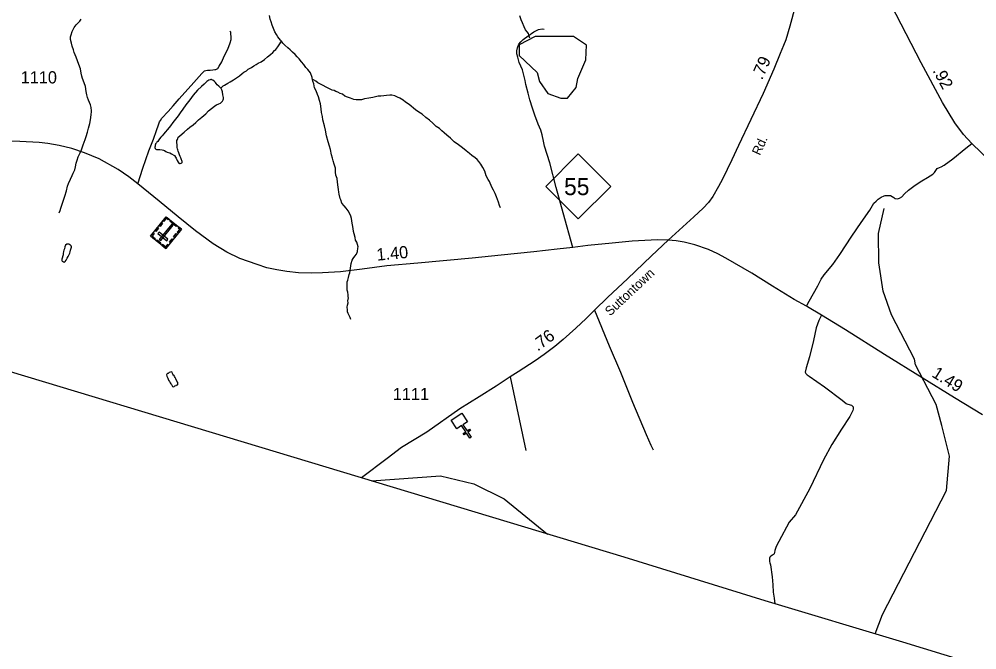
# Model space of a CAD drawing. Extents: x 2206922 to 2357709, y 510027 to 673830.
# Drawn here: x 2238043 to 2247869, y 531268 to 537738 of the extents above; entities that cross this region are included whole.
import ezdxf

# ---------------------------------------------------------------- set-up
doc = ezdxf.new("R2010")
doc.units = 0
for name, color, linetype in [('Exist Boundary Political CountyLine', 7, 'Continuous'), ('Exist Cultural Cemetery CELL', 7, 'Continuous'), ('Exist Cultural Church CELL', 7, 'Continuous'), ('Exist Hydrographic Creek Single Shore', 7, 'Continuous'), ('Exist Hydrographic Misc Water Feature', 7, 'Continuous'), ('Exist Hydrographic Pond Under 1500 Sq Ft', 7, 'Continuous'), ('Exist Road Non-System Type 51', 7, 'Continuous'), ('Exist Road Primary NC Attributed', 7, 'Continuous'), ('Exist Road Primary NC Service Mileage Hundredths English Label', 7, 'Continuous'), ('Exist Road Primary NC Shield CELL', 7, 'Continuous'), ('Exist Road Primary NC Shield Number Label', 7, 'Continuous'), ('Exist Road Secondary Mileage Hundredths English Label', 7, 'Continuous'), ('Exist Road Secondary Type 51 Attributed', 7, 'Continuous'), ('Exist Road Secondary Type 51 Label', 7, 'Continuous'), ('Exist Road Secondary Type 51 Number Label', 7, 'Continuous')]:
    doc.layers.add(name, color=color, linetype=linetype)

msp = doc.modelspace()

# ---------------------------------------------------------------- linework, layer by layer
at = {"layer": 'Exist Boundary Political CountyLine'}
msp.add_lwpolyline([(2249888.1, 524898.7), (2249941, 525530.8), (2250030.4, 526573), (2250196.9, 528467.4), (2250367.4, 530347.8), (2247109, 531346.9), (2245696.1, 531771.2), (2244251.2, 532217.2), (2233874.7, 535351.4), (2230309.4, 536443.8), (2228714.2, 536942.6), (2228202.8, 537099.5)], dxfattribs=at)
at = {"layer": 'Exist Cultural Cemetery CELL'}
for points in [[(2239547.8, 535386.5), (2239392.7, 535511.3), (2239552.3, 535709.7), (2239707.4, 535584.9)], [(2239578.1, 535689), (2239570.9, 535680), (2239553.8, 535693.8), (2239528.4, 535662.3), (2239519.8, 535669.3), (2239552.3, 535709.7)], [(2239474.5, 535594.9), (2239447.4, 535561.2), (2239438.5, 535568.3), (2239465.6, 535602.1)], [(2239515.8, 535646.3), (2239488.7, 535612.5), (2239479.8, 535619.7), (2239507, 535653.4)], [(2239481.2, 535477.7), (2239495.8, 535466), (2239622.9, 535624), (2239608.3, 535635.7)], [(2239655.4, 535612), (2239589.3, 535665.2), (2239596.5, 535674.1), (2239662.6, 535620.9)], [(2239681.6, 535605.6), (2239674.4, 535596.7), (2239691.5, 535582.9), (2239666.2, 535551.4), (2239674.9, 535544.4), (2239707.4, 535584.9)], [(2239419.8, 535545.2), (2239428.6, 535538), (2239408.5, 535513), (2239440.1, 535487.5), (2239433.1, 535478.9), (2239392.7, 535511.4)], [(2239558.7, 535465.1), (2239570.4, 535479.7), (2239478.6, 535553.5), (2239466.9, 535538.9)], [(2239663.6, 535530.4), (2239636.4, 535496.7), (2239627.6, 535503.8), (2239654.7, 535537.5)], [(2239490.1, 535433), (2239449.7, 535465.5), (2239456.9, 535474.3), (2239497.2, 535441.9)], [(2239575, 535420.3), (2239566.1, 535427.4), (2239545.9, 535402.3), (2239514.3, 535427.7), (2239507.4, 535419.1), (2239547.8, 535386.5)], [(2239621.4, 535478), (2239594.3, 535444.3), (2239585.4, 535451.4), (2239612.6, 535485.2)]]:
    msp.add_lwpolyline(points, close=True, dxfattribs=at)
at = {"layer": 'Exist Cultural Church CELL'}
msp.add_lwpolyline([(2242644.1, 533608.1), (2242596.7, 533576.6), (2242638.7, 533513), (2242665.4, 533530.7), (2242674.2, 533517.4), (2242647.5, 533499.7), (2242680.6, 533449.6), (2242667.3, 533440.7), (2242634.1, 533490.9), (2242607.4, 533473.2), (2242598.6, 533486.6), (2242625.3, 533504.2), (2242583.3, 533567.7), (2242535.1, 533536), (2242476.4, 533624.8), (2242585.4, 533696.9)], close=True, dxfattribs=at)
at = {"layer": 'Exist Hydrographic Creek Single Shore'}
for points in [[(2246827.2, 531431.6), (2246901.5, 531630.5), (2247557.6, 532902.9), (2247588.6, 533253.3), (2247510.5, 533569.7), (2247450.6, 533784.1), (2247238.6, 534191.7), (2247230.6, 534251), (2246993.5, 534705), (2246907.6, 534946.2), (2246863.5, 535239), (2246861.5, 535537.5), (2246917.5, 535795.5)], [(2241658.7, 533000.3), (2242367.6, 533053.4), (2242709.4, 532971.1), (2243018.4, 532817.2), (2243464.8, 532454.8)]]:
    msp.add_lwpolyline(points, dxfattribs=at)
at = {"layer": 'Exist Hydrographic Misc Water Feature'}
for points in [[(2240733.9, 537512), (2240723.5, 537524.1), (2240697.2, 537557.7), (2240683.5, 537579.6), (2240666.7, 537609.3), (2240652.9, 537643.4), (2240638.2, 537675.3), (2240628.1, 537709.2), (2240619.9, 537737.2), (2240611.7, 537777)], [(2243284.1, 537542.7), (2243273.7, 537576.7), (2243267.9, 537590.5), (2243255.6, 537608.6), (2243238, 537630.3), (2243223.4, 537658), (2243207, 537699.9), (2243194.7, 537730.1), (2243180.2, 537773.6)], [(2238453.3, 535750.5), (2238465, 535774.3), (2238472.6, 535800.4), (2238482.4, 535830.5), (2238500.1, 535880.6), (2238513.6, 535920.7), (2238529.2, 535976.7), (2238538.6, 536023.2), (2238550.9, 536052.9), (2238568.6, 536095.3), (2238586, 536133.2), (2238597.9, 536159.4), (2238613.5, 536193.6), (2238621.3, 536223.6), (2238629.1, 536259.7), (2238638.7, 536291.5), (2238648.1, 536325.8), (2238668.2, 536367.8), (2238682, 536398.2), (2238699.6, 536448.2), (2238720.7, 536504.2), (2238731, 536534.3), (2238746.3, 536578.2), (2238753.9, 536618.4), (2238767.7, 536668.7), (2238777.1, 536704.6), (2238778.9, 536728.6), (2238782.6, 536758.4), (2238786.9, 536786.6), (2238786.3, 536798.5), (2238782.2, 536832.7), (2238775.9, 536860.4), (2238764.2, 536884.5), (2238753.7, 536908.4), (2238745.3, 536934.4), (2238739.2, 536962.1), (2238732.6, 536994.3), (2238724.2, 537045.9), (2238711.9, 537083.8), (2238692, 537129.8), (2238685.6, 537153.5), (2238679.5, 537185.6), (2238673.3, 537229.5), (2238656.7, 537271.3), (2238642.4, 537309.2), (2238628.2, 537347), (2238619.8, 537371), (2238607.5, 537396.8), (2238599.5, 537424.7), (2238587, 537462.7), (2238581.1, 537492.4), (2238570.8, 537530.5), (2238570.4, 537556.4), (2238576.4, 537578.7), (2238587.8, 537612.6), (2238598.1, 537630.6), (2238607.7, 537652.6), (2238617.8, 537666.9), (2238629.5, 537679), (2238645.3, 537697.3), (2238665.1, 537719), (2238679.1, 537739.2)], [(2240111.8, 537031.3), (2240137.6, 537053.3), (2240151.8, 537061.7), (2240183.8, 537080), (2240209.4, 537096), (2240243.4, 537114.4), (2240275, 537136.3), (2240304.7, 537156.6), (2240332.8, 537179.1), (2240348.2, 537195.1), (2240376.5, 537209.4), (2240394.1, 537223.4), (2240426.1, 537243.8), (2240449.9, 537260), (2240476.2, 537273.9), (2240495.6, 537286.4), (2240525.6, 537300.5), (2240559.4, 537322.6), (2240591.4, 537351), (2240620.9, 537375.4), (2240644.7, 537395.3), (2240664.6, 537415.4), (2240678.5, 537427.5), (2240696, 537453.7), (2240712.2, 537476), (2240733.9, 537512)], [(2241052.8, 537114.8), (2241048.7, 537138.9), (2241032.5, 537186.8), (2241004, 537220.3), (2240983.9, 537242.4), (2240963.8, 537274.2), (2240941.6, 537299.8), (2240915, 537331.8), (2240897.1, 537351.5), (2240874.6, 537377.2), (2240848.9, 537399), (2240822.7, 537422.8), (2240800.1, 537442.8), (2240770.2, 537470.4), (2240747.9, 537492.1), (2240733.9, 537512)], [(2240111.8, 537031.3), (2240106, 537037.4), (2240091.7, 537051.3), (2240075.7, 537065), (2240065.9, 537076.7), (2240057.7, 537088.9), (2240043.5, 537100.7), (2240031.4, 537112.7), (2240021.4, 537116.6), (2240015.4, 537118.3), (2240011.5, 537118.5), (2240001.5, 537116.4), (2239989.2, 537112.1), (2239969.5, 537098.1), (2239941.8, 537071.9), (2239913.9, 537047.7), (2239872.3, 537009.4), (2239828.6, 536957.1), (2239793.3, 536910.6), (2239755.2, 536860.3), (2239722, 536816.3), (2239695.9, 536778.1), (2239674.4, 536747.7), (2239647.1, 536711.6), (2239619.2, 536677.3), (2239595.3, 536645.2), (2239565.9, 536607.1), (2239542.1, 536578.7), (2239526.4, 536560.7), (2239510.2, 536542.5), (2239498.5, 536528.5), (2239484.3, 536510.3), (2239476.7, 536500.5), (2239464.8, 536484.5), (2239457.1, 536476.3), (2239453, 536470), (2239442.9, 536460.2), (2239441.1, 536454), (2239439.2, 536446.1), (2239437.2, 536435.9), (2239435.1, 536426.1), (2239435.3, 536422), (2239439.6, 536412), (2239445.4, 536404.3), (2239451.5, 536400.1), (2239469.4, 536402.3), (2239487.2, 536402.4), (2239509.1, 536398.7), (2239525.5, 536394.6), (2239535.4, 536390.7), (2239549.7, 536379.2), (2239561.8, 536372.9), (2239587.7, 536365.3), (2239607.8, 536357.5), (2239631.8, 536341.7), (2239637.9, 536337.9), (2239648, 536323.8), (2239655.7, 536312.1), (2239666.2, 536288.2), (2239676.5, 536272.1), (2239682.4, 536262.3), (2239688.6, 536258.1), (2239696.1, 536258.2), (2239706.2, 536260.3), (2239712.5, 536264.2), (2239714.4, 536268.4), (2239714.4, 536278.5), (2239712.3, 536288.6), (2239708.4, 536296.4), (2239702.1, 536314.4), (2239695.9, 536330.4), (2239689.6, 536346), (2239681.4, 536366.2), (2239675.6, 536382.1), (2239671.3, 536397.7), (2239667, 536408.1), (2239665.2, 536421.8), (2239665.2, 536431.9), (2239662.9, 536453.8), (2239662.7, 536468), (2239662.7, 536481.8), (2239662.7, 536493.9), (2239666.4, 536503.9), (2239670.7, 536513.8), (2239676.5, 536525.9), (2239688.4, 536537.9), (2239715.8, 536562.2), (2239738, 536580.3), (2239771.4, 536608.5), (2239795.2, 536630.9), (2239827.4, 536653.2), (2239856.9, 536677.1), (2239884.6, 536705.4), (2239918.6, 536733.9), (2239958, 536766.1), (2239985.9, 536796.4), (2240015.4, 536822.7), (2240030, 536830.7), (2240051.7, 536848.9), (2240069.5, 536858.8)], [(2242982.5, 535803.1), (2242972.5, 535826.9), (2242962.2, 535858.9), (2242949.7, 535886.7), (2242939.5, 535916.6), (2242925.7, 535948.7), (2242911.4, 535982.5), (2242892.7, 536014.1), (2242868.3, 536074.2), (2242856.4, 536093.8), (2242835.9, 536131.8), (2242819.7, 536177.6), (2242801.5, 536215.7), (2242780.9, 536251.2), (2242760.4, 536279), (2242743, 536299.1), (2242720.5, 536314.6), (2242688.3, 536338.5), (2242662.2, 536360.3), (2242630, 536385.9), (2242591.7, 536419.6), (2242549.6, 536447.5), (2242507.2, 536481), (2242468.9, 536516.8), (2242430.5, 536546.5), (2242404.7, 536570.3), (2242380.3, 536591.8), (2242356.3, 536615.7), (2242322.5, 536637.5), (2242288, 536671), (2242254, 536700.9), (2242217.3, 536728.7), (2242177.5, 536762.3), (2242143.2, 536783.7), (2242110.6, 536807.6), (2242044.2, 536861.1), (2242008.1, 536886.7), (2241982.1, 536906.5), (2241949.7, 536926.4), (2241924, 536938), (2241897.8, 536951.6), (2241865.6, 536959.4), (2241847.8, 536959.2), (2241813.7, 536955), (2241783.6, 536952.7), (2241754, 536948.6), (2241728.2, 536946.4), (2241672, 536933.8), (2241632.5, 536927.6), (2241585.9, 536919.2), (2241556.2, 536911.1), (2241522.1, 536910.6), (2241502, 536910.8), (2241478, 536914.4), (2241460.4, 536920.3), (2241442, 536928), (2241412.2, 536937.7), (2241385.8, 536947.7), (2241359.7, 536967.5), (2241338.2, 536975.2), (2241313.6, 536989.1), (2241291.7, 536996.9), (2241275.5, 537004.5), (2241255.6, 537010.4), (2241221.7, 537026.4), (2241191.6, 537042), (2241163.1, 537057.6), (2241109.2, 537083.2), (2241087, 537101.1), (2241064.7, 537115), (2241052.8, 537114.8)], [(2241446.9, 534657.2), (2241440.5, 534677.2), (2241428, 534696.9), (2241418.2, 534717.1), (2241412.2, 534737), (2241412, 534756.9), (2241410, 534784.8), (2241413.3, 534803), (2241417.4, 534827.1), (2241417.1, 534849), (2241420.8, 534878.9), (2241420.6, 534885), (2241419, 534910.8), (2241416.5, 534936.7), (2241410, 534956.7), (2241409.6, 535012.8), (2241409.4, 535044.8), (2241415.5, 535061), (2241423.3, 535086.9), (2241429, 535116.9), (2241435, 535137.1), (2241440.3, 535159), (2241446.3, 535207.2), (2241449.7, 535230.9), (2241459.8, 535265.1), (2241471.3, 535281.2), (2241487.7, 535305.1), (2241503.3, 535325.5), (2241513.1, 535353.2), (2241518.6, 535389.7), (2241520.5, 535403.5), (2241514.5, 535425.5), (2241508.2, 535449.2), (2241495.7, 535471.4), (2241491.8, 535499.1), (2241481.7, 535535.1), (2241475.2, 535559.2), (2241468.8, 535591), (2241462.5, 535628.8), (2241460.4, 535645), (2241452.2, 535692.8), (2241445.9, 535718.5), (2241434, 535748.7), (2241419.8, 535770.3), (2241399.5, 535800.1), (2241377.4, 535822.2), (2241355, 535851.8), (2241342.9, 535885.7), (2241338.4, 535899.8), (2241327.9, 535941.5), (2241324.1, 535963.6), (2241318.1, 535989.6), (2241317.7, 536015.6), (2241311.1, 536065.3), (2241305.2, 536103.5), (2241292.5, 536137.4), (2241288.6, 536169.3), (2241288.4, 536209), (2241275.9, 536249), (2241265.2, 536285.1), (2241259.3, 536312.8), (2241249.2, 536346.7), (2241236.3, 536402.6), (2241226.2, 536436.6), (2241213.7, 536478.6), (2241197.5, 536542.3), (2241186.9, 536598.2), (2241174.6, 536644.3), (2241160.2, 536706), (2241154.1, 536739.8), (2241145.2, 536779.7), (2241143.2, 536817.7), (2241136.4, 536869.8), (2241126.4, 536903.4), (2241114.1, 536939.7), (2241104, 536963.5), (2241089.9, 537003.4), (2241073.5, 537035), (2241066.9, 537074.9), (2241056.9, 537100.8), (2241052.8, 537114.8)], [(2240069.5, 536858.8), (2240091.7, 536869.2), (2240109.1, 536877.2), (2240121.4, 536889.5), (2240129, 536897.7), (2240135, 536909.8), (2240138.6, 536919.7), (2240138.9, 536935.5), (2240134.5, 536963.3), (2240128.2, 536991.5), (2240122, 537011.4), (2240115.9, 537027.4), (2240111.8, 537031.3)], [(2238531.4, 535431.4), (2238520, 535421), (2238513.8, 535401.2), (2238508.1, 535383), (2238501.9, 535368.9), (2238498.4, 535354.9), (2238496.4, 535332.9), (2238494.9, 535318.9), (2238489, 535300.8), (2238487.2, 535295), (2238484.9, 535286.8), (2238482.9, 535276.9), (2238481.4, 535270.7), (2238481.4, 535263), (2238483.3, 535257), (2238497.2, 535248.8), (2238505.2, 535243.1), (2238517.1, 535253.1), (2238527.1, 535265.4), (2238537, 535285.4), (2238546.8, 535303.4), (2238552.6, 535315.5), (2238562.2, 535337.6), (2238566.7, 535351.5), (2238570.2, 535367.6), (2238573.9, 535377.6), (2238575.9, 535387.4), (2238579.8, 535397.8), (2238580, 535403.4), (2238578, 535411.4), (2238570, 535419.5), (2238563.6, 535423.3), (2238551.5, 535429.6), (2238543.8, 535431.2), (2238537.4, 535431.3), (2238531.4, 535431.4)], [(2239608, 534118.6), (2239581.9, 534112.4), (2239577.8, 534108.2), (2239573.7, 534104.3), (2239566.1, 534104.2), (2239557.9, 534096.2), (2239556.3, 534088.3), (2239560.2, 534074.3), (2239568.4, 534054.5), (2239576.6, 534034.6), (2239584.4, 534020.4), (2239593.2, 534006.5), (2239599.2, 533998.3), (2239607.2, 533990.6), (2239610.8, 533984.8), (2239617, 533970.9), (2239629.1, 533966.6), (2239641, 533975), (2239652.9, 533978.8), (2239659, 533985.3), (2239667, 533985.3), (2239672.8, 533989.3), (2239672.6, 534011.1), (2239662.7, 534023.2), (2239650.6, 534046.9), (2239644.3, 534060.8), (2239636.3, 534071), (2239632.4, 534080.9), (2239626, 534086.7), (2239620.1, 534096.5), (2239618, 534104.5), (2239611.9, 534116.4), (2239608, 534118.6)]]:
    msp.add_lwpolyline(points, dxfattribs=at)
at = {"layer": 'Exist Hydrographic Pond Under 1500 Sq Ft'}
msp.add_lwpolyline([(2243668.4, 536926.8), (2243759.5, 537036.5), (2243775.5, 537128), (2243856.4, 537319.9), (2243864.4, 537470.7), (2243729.5, 537561.9), (2243338.5, 537559.9), (2243172.4, 537474.7), (2243173.4, 537366.5), (2243358.4, 537192.2), (2243383.4, 537099.8), (2243468.5, 536976.8), (2243601.6, 536928.2), (2243668.4, 536926.8)], dxfattribs=at)
at = {"layer": 'Exist Road Non-System Type 51'}
msp.add_line((2243080.6, 534068.8), (2243242.7, 533312.6), dxfattribs=at)
for points in [[(2239260, 536048.5), (2239312.5, 536210.8), (2239375.4, 536387.2), (2239422.6, 536508.4), (2239452.5, 536595), (2239471.4, 536654.8), (2239482.4, 536684.7), (2239493.4, 536698.9), (2239507.6, 536722.5), (2239573.7, 536790.2), (2239624, 536848.4), (2239685.4, 536920.9), (2239834.9, 537089.3), (2239916.7, 537179.1), (2239938.7, 537202.7), (2239946.6, 537209), (2239959.2, 537212.1), (2239974.9, 537215.3), (2240003.2, 537215.3), (2240031.6, 537216.8), (2240050.4, 537220), (2240063, 537223.1), (2240080.3, 537232.6), (2240096.1, 537254.6), (2240121.2, 537298.7), (2240148, 537358.5), (2240184.2, 537430.9), (2240209.3, 537496.3), (2240218.8, 537530.9), (2240218.8, 537559.3), (2240215.6, 537584.4), (2240214.1, 537604.9), (2240204.6, 537614.4)], [(2243722.5, 535396.9), (2243625, 535750.2), (2243551.4, 536009.6), (2243486.7, 536265.1), (2243432.3, 536435.6), (2243421.8, 536486.4), (2243409.5, 536553), (2243395.5, 536600.4), (2243369.2, 536660), (2243334.2, 536752.9), (2243309.6, 536824.7), (2243281.6, 536908.9), (2243264.1, 536977.2), (2243243.1, 537066.6), (2243234.3, 537108.7), (2243206.3, 537219.1), (2243174.7, 537294.5), (2243159, 537348.8), (2243150.2, 537382.1), (2243148.5, 537411.9), (2243155.5, 537443.5), (2243171.2, 537480.3), (2243188.8, 537504.8), (2243215, 537529.4), (2243264.1, 537566.2), (2243325.4, 537606.5), (2243372.7, 537632.8), (2243407.7, 537638), (2243430.5, 537634.5)], [(2246122, 534793.4), (2246147.8, 534844.9), (2246238.9, 535002.7), (2246270.4, 535069.3), (2246303.7, 535114.8), (2246391.3, 535221.8), (2246464.9, 535325.2), (2246587.5, 535512.7), (2246682.1, 535653), (2246769.7, 535779.2), (2246813.5, 535849.3), (2246834.5, 535872.1), (2246855.5, 535891.4), (2246888.8, 535912.4), (2246916.8, 535926.4), (2246929.1, 535928.2), (2246939.6, 535928.2), (2246955.4, 535929.9), (2246967.6, 535929.9), (2246981.7, 535928.2), (2246999.2, 535917.6), (2247018.4, 535907.1), (2247029, 535898.4), (2247034.2, 535896.6), (2247053.5, 535894.9), (2247076.3, 535900.1), (2247099, 535915.9), (2247127.1, 535945.7), (2247169.1, 535984.3), (2247237.4, 536033.3), (2247304, 536080.7), (2247363.6, 536112.2), (2247416.1, 536147.3), (2247435.4, 536164.8), (2247449.4, 536185.8), (2247463.4, 536205.1), (2247484.4, 536215.6), (2247502, 536224.4), (2247535.3, 536240.2), (2247621.1, 536305), (2247756, 536415.5), (2247817.3, 536461)], [(2243946.2, 534751.9), (2244095.7, 534386.1), (2244213.6, 534116.2), (2244335.1, 533807.7), (2244476.4, 533475.8), (2244523.1, 533367.1), (2244547.6, 533319.2)], [(2246275.6, 534702), (2246249.3, 534647.7), (2246221.3, 534570.6), (2246191.5, 534440.8), (2246152.9, 534274.3), (2246117.9, 534160.4), (2246107.4, 534116.6), (2246112.7, 534104.3), (2246126.7, 534088.5), (2246149.4, 534074.5), (2246305.4, 533965.8), (2246487.6, 533829.1), (2246529.6, 533795.8), (2246536.2, 533791.4), (2246546.8, 533788.2), (2246559.1, 533786.4), (2246570.6, 533782.3), (2246582.6, 533777), (2246592.9, 533768.8), (2246599.4, 533760.3), (2246601.4, 533752), (2246601.2, 533737.3), (2246597.9, 533722.2), (2246564.6, 533662.6), (2246480.5, 533531.1), (2246382.4, 533373.4), (2246296.6, 533215.6), (2246156.4, 532924.6), (2246007.5, 532651.2), (2245944.5, 532579.3), (2245838, 532379.7), (2245810, 532327.5), (2245797.5, 532286.2), (2245792.1, 532265.2), (2245788.2, 532253.5), (2245781.2, 532246.5), (2245771, 532238.7), (2245757, 532228.6), (2245745.3, 532218.4), (2245740.7, 532208.3), (2245740.7, 532194.3), (2245743, 532175.6), (2245746.1, 532160), (2245753.1, 532139.7), (2245767.5, 532018.4), (2245774.5, 531936), (2245779.8, 531860.6), (2245788.6, 531799.3), (2245797.9, 531740.7)]]:
    msp.add_lwpolyline(points, dxfattribs=at)
at = {"layer": 'Exist Road Primary NC Attributed'}
for points in [[(2244700.6, 535469.4), (2244592, 535474.1), (2244332.8, 535460.3), (2244127, 535438.7), (2243879.4, 535414.7), (2243722.5, 535396.9), (2243561.9, 535378.6), (2243325.4, 535352.3), (2242987.3, 535317.3), (2242691.2, 535285.7), (2242133.6, 535234.5), (2241814.1, 535205.9), (2241562.5, 535174), (2241341.9, 535146.8), (2241156.4, 535134.2), (2241041, 535130.6), (2240907.7, 535134.2), (2240788.8, 535148.6), (2240686.1, 535166.6), (2240585.2, 535188.3), (2240484.3, 535220.7), (2240307.7, 535281.1), (2240172.6, 535346), (2240033, 535433.3), (2239851.9, 535565), (2239675.3, 535709.3), (2239478.9, 535869.7), (2239315, 536004.9), (2239260, 536048.5), (2239167.2, 536122.1), (2239059.1, 536194.2), (2238862.7, 536304.2), (2238713.2, 536365.5), (2238583.4, 536410.5), (2238453.7, 536443), (2238336.6, 536462.8), (2238250.1, 536473.6), (2238050.9, 536483.3), (2237715.1, 536486.8)], [(2247927.7, 533679.3), (2247640.4, 533852.8), (2247308.8, 534057.2), (2246923, 534297.9), (2246521, 534550.5), (2246275.6, 534702), (2246131.9, 534787.9), (2246122, 534793.4), (2245995.3, 534863.3), (2245771, 535000), (2245559.1, 535131.5), (2245292.8, 535285.7), (2245210.4, 535331.3), (2245115.8, 535373.4), (2244973.9, 535424.2), (2244865.3, 535450.5), (2244782.4, 535462.4), (2244700.6, 535469.4)]]:
    msp.add_lwpolyline(points, dxfattribs=at)
at = {"layer": 'Exist Road Primary NC Shield CELL'}
msp.add_lwpolyline([(2243446.8, 536022.5), (2243779.8, 536355.5), (2244112.8, 536022.5), (2243779.8, 535689.5)], close=True, dxfattribs=at)
at = {"layer": 'Exist Road Secondary Type 51 Attributed'}
for points in [[(2249053.2, 535325.7), (2248961.7, 535409.6), (2248802.4, 535556.8), (2248552.5, 535784.2), (2248442.1, 535882.4), (2248012.1, 536273.9), (2247817.3, 536461), (2247733, 536554.2), (2247642.4, 536675.9), (2247516.1, 536884.4), (2247298.2, 537290.2), (2247042.7, 537784.6), (2246844.6, 538162.9), (2246666.4, 538501.7), (2246453.3, 538907.4), (2246265.9, 539255.6)], [(2246006.3, 537866.9), (2245949.1, 537666.3), (2245909.4, 537527.2), (2245886.1, 537468.8), (2245851, 537385.8), (2245785.7, 537225.3), (2245675.9, 536975.7), (2245550.9, 536708.1), (2245424.7, 536440.5), (2245353.5, 536293.2), (2245258.9, 536096.9), (2245219.2, 536020.9), (2245159.6, 535918.1), (2245114.1, 535856.2), (2245061.5, 535800.1), (2244966.9, 535711.3), (2244852.5, 535606.1), (2244700.6, 535469.4)], [(2244700.6, 535469.4), (2244530.1, 535311.6), (2244283.7, 535074.4), (2244082.8, 534886.3), (2243946.2, 534751.9), (2243859.7, 534665.4), (2243755.8, 534567.3), (2243625, 534452.7), (2243538.6, 534378.3), (2243429.9, 534297.7), (2243338.8, 534233.4), (2243162.2, 534121.5), (2243080.6, 534068.8), (2242937.5, 533971.7), (2242763.1, 533861.8), (2242565.7, 533739.1), (2242227.7, 533502.1), (2241967.1, 533342), (2241820.1, 533231), (2241555.4, 533031.5)]]:
    msp.add_lwpolyline(points, dxfattribs=at)

# ---------------------------------------------------------------- texts
at = {"layer": 'Exist Road Primary NC Service Mileage Hundredths English Label'}
for s, rotation, p in [('1.40', 5.11501, (2241715.5, 535259.9)), ('1.49', 328.34162, (2247398.6, 534075.3))]:
    msp.add_text(s, height=125, rotation=rotation, dxfattribs=at).set_placement(p)
at = {"layer": 'Exist Road Primary NC Shield Number Label'}
msp.add_text('55', height=175, dxfattribs=at).set_placement((2243634, 535932.8))
at = {"layer": 'Exist Road Secondary Mileage Hundredths English Label'}
for s, rotation, p in [('.79', 66.24922, (2245665.9, 537108.3)), ('.92', 298.23179, (2247412.1, 537210.2)), ('.76', 36.58815, (2243363.7, 534326.4))]:
    msp.add_text(s, height=125, rotation=rotation, dxfattribs=at).set_placement(p)
at = {"layer": 'Exist Road Secondary Type 51 Label'}
for s, rotation, p in [('Rd.', 65.55415, (2245643.4, 536333.9)), ('Suttontown', 43.0812, (2244106.7, 534687.4))]:
    msp.add_text(s, height=95, rotation=rotation, dxfattribs=at).set_placement(p)
at = {"layer": 'Exist Road Secondary Type 51 Number Label'}
for s, p in [('1110', (2238059.2, 537078.8)), ('1111', (2241876.8, 533829.4))]:
    msp.add_text(s, height=125, dxfattribs=at).set_placement(p)

doc.saveas('drawing.dxf')
